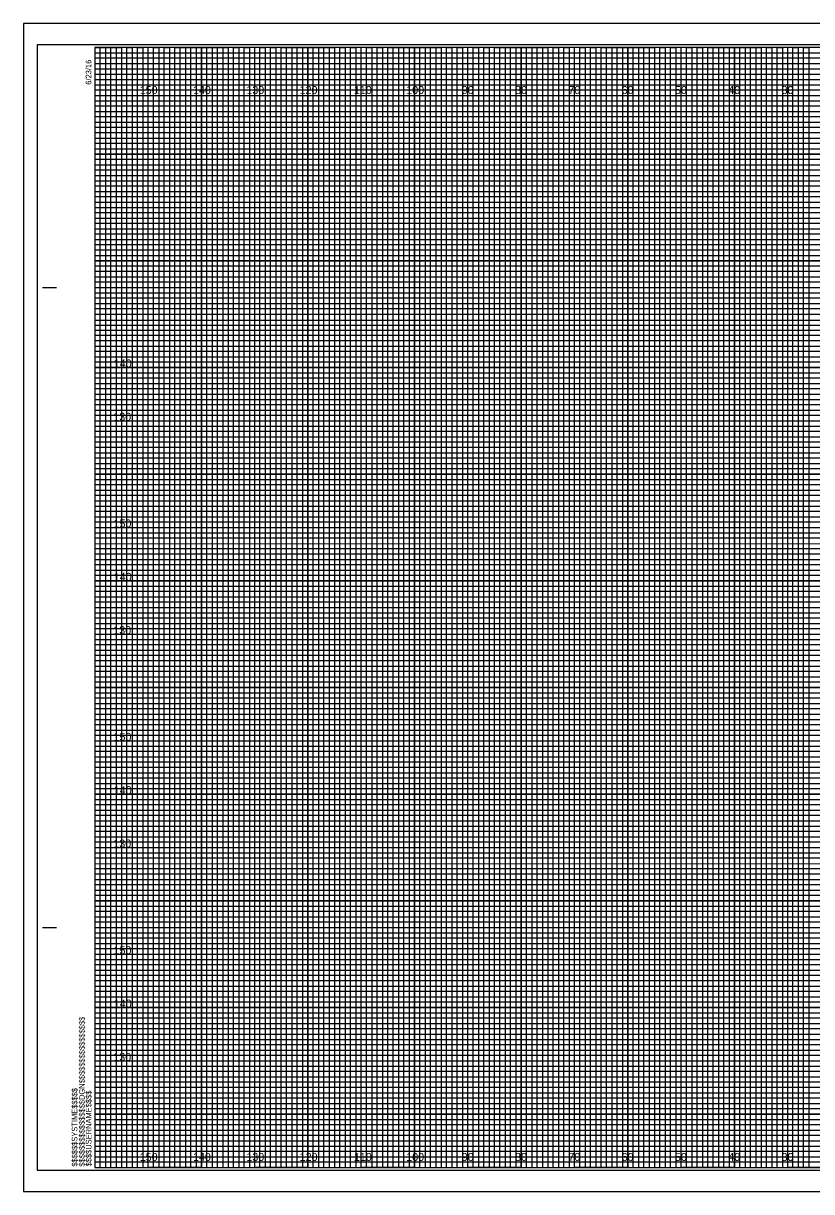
# Model space of a CAD drawing. Extents: x -13 to 323, y -5 to 434.
# Drawn here: x -13.4 to 134.5, y 215.5 to 434.5 of the extents above; entities that cross this region are included whole.
import ezdxf

# ---------------------------------------------------------------- set-up
doc = ezdxf.new("R2010")
doc.units = 0
for name, color, linetype in [('Exist Cross Section Cell', 7, 'Continuous'), ('Exist XS Center Line Elevation Label', 7, 'Continuous'), ('Exist XS Ground Line', 7, 'Continuous'), ('Prop CMT Pvmt Course 2', 7, 'Continuous'), ('Prop CMT Pvmt Course 3', 7, 'Continuous'), ('Prop CMT Pvmt Surface', 7, 'Continuous'), ('Prop CMT Pvmt Surface Shoulder', 7, 'Continuous'), ('Prop CMT Shld Paved Course 1', 7, 'Continuous'), ('Prop CMT Shld Paved Course 2', 7, 'Continuous'), ('Prop CMT Shld Paved Course 3', 7, 'Continuous'), ('Prop CMT Subgrade Earthwork', 7, 'Continuous')]:
    doc.layers.add(name, color=color, linetype=linetype)

msp = doc.modelspace()

# ---------------------------------------------------------------- linework, layer by layer
at = {"layer": 'Exist XS Center Line Elevation Label'}
for points in [[(0, 430), (5, 430), (5, 220), (15, 220), (15, 430), (25, 430), (25, 220), (35, 220), (35, 430), (45, 430), (45, 220), (55, 220), (55, 430), (65, 430), (65, 220), (75, 220), (75, 430), (85, 430), (85, 220), (95, 220), (95, 430), (105, 430), (105, 220), (115, 220), (115, 430), (125, 430), (125, 220), (135, 220)], [(0, 425), (275, 425)], [(0, 405), (320, 405), (320, 415), (0, 415)], [(0, 385), (320, 385), (320, 395), (0, 395)], [(0, 365), (320, 365), (320, 375), (0, 375)], [(0, 345), (320, 345), (320, 355), (0, 355)], [(0, 325), (320, 325), (320, 335), (0, 335)], [(0, 305), (320, 305), (320, 315), (0, 315)], [(0, 285), (320, 285), (320, 295), (0, 295)], [(0, 265), (320, 265), (320, 275), (0, 275)], [(0, 245), (320, 245), (320, 255), (0, 255)], [(0, 225), (320, 225), (320, 235), (0, 235)]]:
    msp.add_lwpolyline(points, dxfattribs=at)
at = {"layer": 'Exist XS Ground Line'}
for p, q in [((10, 430), (0, 430)), ((10, 220), (10, 430)), ((30, 430), (20, 430)), ((20, 430), (20, 220)), ((30, 220), (30, 430)), ((50, 430), (40, 430)), ((40, 430), (40, 220)), ((50, 220), (50, 430)), ((70, 430), (60, 430)), ((60, 430), (60, 220)), ((70, 220), (70, 430)), ((90, 430), (80, 430)), ((80, 430), (80, 220)), ((90, 220), (90, 430)), ((110, 430), (100, 430)), ((100, 430), (100, 220)), ((110, 220), (110, 430)), ((130, 430), (120, 430)), ((120, 430), (120, 220)), ((130, 220), (130, 430)), ((20, 220), (10, 220)), ((40, 220), (30, 220)), ((60, 220), (50, 220)), ((80, 220), (70, 220)), ((100, 220), (90, 220)), ((120, 220), (110, 220)), ((140, 220), (130, 220))]:
    msp.add_line(p, q, dxfattribs=at)
for points in [[(0, 420), (320, 420), (320, 410), (0, 410)], [(0, 400), (320, 400), (320, 390), (0, 390)], [(0, 380), (320, 380), (320, 370), (0, 370)], [(0, 360), (320, 360), (320, 350), (0, 350)], [(0, 340), (320, 340), (320, 330), (0, 330)], [(0, 320), (320, 320), (320, 310), (0, 310)], [(0, 300), (320, 300), (320, 290), (0, 290)], [(0, 280), (320, 280), (320, 270), (0, 270)], [(0, 260), (320, 260), (320, 250), (0, 250)], [(0, 240), (320, 240), (320, 230), (0, 230)]]:
    msp.add_lwpolyline(points, dxfattribs=at)
at = {"layer": 'Prop CMT Pvmt Course 2'}
for p, q in [((0, 429), (260, 429)), ((260, 427.98), (0, 427.98)), ((0, 427.98), (0, 427)), ((0, 427), (260, 427)), ((260, 425.89), (0, 425.89)), ((0, 425.89), (0, 424)), ((0, 424), (320, 424))]:
    msp.add_line(p, q, dxfattribs=at)
for points in [[(0, 423), (270, 423), (320, 423), (320, 422), (0, 422)], [(0, 421), (320, 421), (320, 419), (0, 419)], [(0, 418), (320, 418), (320, 417), (0, 416.98)], [(0, 416), (320, 416), (320, 414), (0, 414)], [(0, 413), (320, 413), (320, 412), (0, 412)], [(0, 411), (320, 411), (320, 409), (0, 409)], [(0, 408), (320, 408), (320, 407), (0, 407)], [(0, 406), (320, 406), (320, 404), (0, 404)], [(0, 403), (320, 403), (320, 402), (0, 402)], [(0, 401), (320, 401), (320, 399), (0, 399)], [(0, 398), (320, 398), (320, 397), (0, 397)], [(0, 396), (320, 396), (320, 393.95), (320, 393), (320, 392), (0, 392)], [(0, 394), (320, 394), (320, 393), (0, 393)], [(0, 391), (320, 391), (320, 389), (0, 389.03)], [(0, 389.03), (320, 389), (320, 388), (0, 388)], [(0, 387), (320, 387), (320, 386), (0, 386)], [(0, 384), (320, 384), (320, 383), (0, 383)], [(0, 382), (320, 382), (320, 381), (0, 381)], [(-0.07, 378.89), (320, 378.89), (320, 377.88), (-0.07, 377.88)], [(0, 377), (320, 377), (320, 376), (0, 376)], [(0, 374), (320, 374), (320, 373), (0, 373)], [(0, 372), (320, 372), (320, 371), (0, 371)], [(0, 369), (320, 369), (320, 368), (0, 368)], [(0, 367), (320, 367), (320, 366), (0, 366)], [(0, 364), (320, 364), (320, 363), (0, 363)], [(0, 362), (320, 362), (320, 361), (0, 361)], [(0, 359), (320, 359), (319.99, 357.98), (0, 358)], [(0, 357), (320, 357), (320, 356), (0, 356)], [(0, 354), (320, 354), (320, 353), (0, 353)], [(0, 352), (320, 352), (320, 351), (0, 351)], [(0, 349), (320, 349), (320, 348), (0, 348)], [(0, 347), (320, 347), (320, 346), (0, 346)], [(0, 344), (320, 344), (320, 343), (0, 343)], [(0, 342), (320, 342), (320, 341), (0, 341)], [(0, 339), (320, 339), (320, 338), (0, 338)], [(0, 336.99), (320.07, 336.91), (320, 336), (0, 336)], [(0, 334), (320, 334), (320, 333), (0, 333)], [(0, 332), (320, 332), (320, 331), (0, 331)], [(0, 329), (320, 329), (320, 328), (0, 328)], [(0, 327), (320, 327), (320, 326), (0, 326)], [(0, 324), (320, 324), (320, 323), (0, 323)], [(0, 322), (320, 322), (320, 321), (0, 321)], [(0, 319), (320, 319), (320, 318), (0, 318)], [(0, 317), (320, 317), (320, 316), (0, 316)], [(0, 314), (320, 314), (320, 313), (0, 313)], [(0, 312), (320, 312), (320, 311), (0, 311)], [(0, 309), (320, 309), (320, 308), (0, 308)], [(0, 307), (320, 307), (320, 306), (0, 306)], [(0, 304), (320, 304), (320, 303), (0, 303)], [(0, 302), (320, 302), (320, 301), (0, 301)], [(0, 299), (320, 299), (319.99, 297.98), (0, 298)], [(0, 297), (320, 297), (320, 296), (0, 296)], [(0, 294), (320, 294), (320, 293), (0, 293)], [(0, 292), (320, 292), (320, 291), (0, 291)], [(0, 289), (320, 289), (320, 288), (0, 288)], [(0, 287), (320, 287), (320, 286), (0, 286)], [(0, 284), (320, 284), (320, 283), (0, 283)], [(0, 282), (320, 282), (320, 281), (0, 281)], [(0, 279), (320, 279), (320, 278), (0, 278)], [(0, 276.99), (320.07, 276.91), (320, 276), (0, 276)], [(0, 274), (320, 274), (320, 273), (0, 273)], [(0, 272), (320, 272), (320, 271), (0, 271)], [(0, 269), (320, 269), (320, 268), (0, 268)], [(0, 267), (320, 267), (320, 266), (0, 266)], [(0, 264), (320, 264), (320, 263), (0, 263)], [(0, 262), (320, 262), (320, 261), (0, 261)], [(0, 259), (320, 259), (320, 258), (0, 258)], [(0, 257), (320, 257), (320, 256), (0, 256)], [(0, 254), (320, 254), (320, 253), (0, 253)], [(0, 252), (320, 252), (320, 251), (0, 251)], [(0, 249), (320, 249), (320, 248), (0, 248)], [(0, 247), (320, 247), (320, 246), (0, 246)], [(0, 244), (320, 244), (320, 243), (0, 243)], [(0, 242), (320, 242), (320, 241), (0, 241)], [(0, 239), (320, 239), (320, 238), (0, 238)], [(0, 237), (320, 237), (320, 236), (0, 236)], [(0, 234), (320, 234), (320, 233), (0, 233)], [(0, 232), (320, 232), (320, 231), (0, 231)], [(0, 229), (320, 229), (320, 228), (0, 228)], [(0, 227), (320, 227), (320, 226), (0, 226)], [(0, 224), (320, 224), (320, 223), (0, 223)], [(0, 222), (320, 222), (320, 221), (0, 221)]]:
    msp.add_lwpolyline(points, dxfattribs=at)
at = {"layer": 'Prop CMT Pvmt Course 3'}
for p, q in [((-9.8, 385), (-7.3, 385)), ((-9.7, 385), (-7.2, 385)), ((-9.8, 265), (-7.3, 265)), ((-9.7, 265), (-7.2, 265)), ((0, 220), (0, 220)), ((0, 220), (0, 220)), ((0, 220), (0, 220)), ((0, 220), (0, 220)), ((0, 220), (0, 220)), ((0, 220), (0, 220)), ((0, 220), (0, 220))]:
    msp.add_line(p, q, dxfattribs=at)
msp.add_lwpolyline([(320, 430), (0, 430), (0, 220), (320, 220)], close=True, dxfattribs=at)
at = {"layer": 'Prop CMT Pvmt Surface'}
for points in [[(0, 220), (1, 220), (1, 430), (2, 430), (2, 220)], [(2, 220), (3, 220), (3, 430), (4, 430), (4, 220)], [(5, 220), (6, 220), (6, 430), (7, 430), (7, 220)], [(7, 220), (8, 220), (8, 430), (9, 430), (9, 220)], [(10, 220), (11, 220), (11, 430), (12, 430), (12, 220)], [(12, 220), (13, 220), (13, 430), (14, 430), (14, 220)], [(15, 220), (16, 220), (16, 430), (17, 430), (17, 220)], [(17, 220), (18, 220), (18, 430), (19, 430), (19, 220)], [(20, 220), (21, 220), (21, 430), (22, 430), (22, 220)], [(22, 220), (23, 220), (23, 430), (24, 430), (24, 220)], [(25, 220), (26, 220), (26, 430), (27, 430), (27, 220)], [(27, 220), (28, 220), (28, 430), (29, 430), (29, 220)], [(30, 220), (31, 220), (31, 430), (32, 430), (32, 220)], [(32, 220), (33, 220), (33, 430), (34, 430), (34, 220)], [(35, 220), (36, 220), (36, 430), (37, 430), (37, 220)], [(37, 220), (38, 220), (38, 430), (39, 430), (39, 220)], [(40, 220), (41, 220), (41, 430), (42, 430), (42, 220)], [(42, 220), (43, 220), (43, 430), (44, 430), (44, 220)], [(45, 220), (46, 220), (46, 430), (47, 430), (47, 220)], [(47, 220), (48, 220), (48, 430), (49, 430), (49, 220)], [(50, 220), (51, 220), (51, 430), (52, 430), (52, 220)], [(52, 220), (53, 220), (53, 430), (54, 430), (54, 220)], [(55, 220), (56, 220), (56, 430), (57, 430), (57, 220)], [(57, 220), (58, 220), (58, 430), (59, 430), (59, 220)], [(60, 220), (61, 220), (61, 430), (62, 430), (62, 220)], [(62, 220), (63, 220), (63, 430), (64, 430), (64, 220)], [(65, 220), (66, 220), (66, 430), (67, 430), (67, 220)], [(67, 220), (68, 220), (68, 430), (69, 430), (69, 220)], [(70, 220), (71, 220), (71, 430), (72, 430), (72, 220)], [(72, 220), (73, 220), (73, 430), (74, 430), (74, 220)], [(75, 220), (76, 220), (76, 430), (77, 430), (77, 220)], [(77, 220), (78, 220), (78, 430), (79, 430), (79, 220)], [(80, 220), (81, 220), (81, 430), (82, 430), (82, 220)], [(82, 220), (83, 220), (83, 430), (84, 430), (84, 220)], [(85, 220), (86, 220), (86, 430), (87, 430), (87, 220)], [(87, 220), (88, 220), (88, 430), (89, 430), (89, 220)], [(90, 220), (91, 220), (91, 430), (92, 430), (92, 220)], [(92, 220), (93, 220), (93, 430), (94, 430), (94, 220)], [(95, 220), (96, 220), (96, 430), (97, 430), (97, 220)], [(97, 220), (98, 220), (98, 430), (99, 430), (99, 220)], [(100, 220), (101, 220), (101, 430), (102, 430), (102, 220)], [(102, 220), (103, 220), (103, 430), (104, 430), (104, 220)], [(105, 220), (106, 220), (106, 430), (107, 430), (107, 220)], [(107, 220), (108, 220), (108, 430), (109, 430), (109, 220)], [(110, 220), (111, 220), (111, 430), (112, 430), (112, 220)], [(112, 220), (113, 220), (113, 430), (114, 430), (114, 220)], [(115, 220), (116, 220), (116, 430), (117, 430), (117, 220)], [(117, 220), (118, 220), (118, 430), (119, 430), (119, 220)], [(120, 220), (121, 220), (121, 430), (122, 430), (122, 220)], [(122, 220), (123, 220), (123, 430), (124, 430), (124, 220)], [(125, 220), (126, 220), (126, 430), (127, 430), (127, 220)], [(127, 220), (128, 220), (128, 430), (129, 430), (129, 220)], [(130, 220), (131, 220), (131, 430), (132, 430), (132, 220)], [(132, 220), (133, 220), (133, 430), (134, 430), (134, 220)]]:
    msp.add_lwpolyline(points, dxfattribs=at)
at = {"layer": 'Prop CMT Pvmt Surface Shoulder'}
msp.add_lwpolyline([(-10.8, 219.5), (322.4, 219.5), (322.4, 430.5), (-10.8, 430.5)], close=True, dxfattribs=at)
at = {"layer": 'Prop CMT Shld Paved Course 1'}
for p, q in [((10, 220), (10, 430)), ((20, 220), (20, 430)), ((30, 220), (30, 430)), ((40, 220), (40, 430)), ((50, 220), (50, 430)), ((60, 220), (60, 430)), ((70, 220), (70, 430)), ((80, 220), (80, 430)), ((90, 220), (90, 430)), ((100, 220), (100, 430)), ((110, 220), (110, 430)), ((120, 220), (120, 430)), ((130, 220), (130, 430)), ((0, 420), (320, 420)), ((0, 410), (320, 410)), ((0, 400), (320, 400)), ((0, 390), (320, 390)), ((0, 380), (320, 380)), ((0, 370), (320, 370)), ((0, 360), (320, 360)), ((0, 350), (320, 350)), ((0, 340), (320, 340)), ((0, 330), (320, 330)), ((0, 320), (320, 320)), ((0, 310), (320, 310)), ((0, 300), (320, 300)), ((0, 290), (320, 290)), ((0, 280), (320, 280)), ((0, 270), (320, 270)), ((0, 260), (320, 260)), ((0, 250), (320, 250)), ((0, 240), (320, 240)), ((0, 230), (320, 230))]:
    msp.add_line(p, q, dxfattribs=at)
at = {"layer": 'Prop CMT Shld Paved Course 2'}
for p, q in [((323.3, 434.5), (-13.4, 434.5)), ((-13.4, 434.5), (-13.4, 215.5)), ((-13.4, 215.5), (323.3, 215.5))]:
    msp.add_line(p, q, dxfattribs=at)
at = {"layer": 'Prop CMT Subgrade Earthwork'}
msp.add_lwpolyline([(-13.4, 215.5), (323.3, 215.5), (323.3, 434.5), (-13.4, 434.5)], close=True, dxfattribs=at)

# ---------------------------------------------------------------- texts
at = {"layer": 'Exist Cross Section Cell'}
for s, p in [('150', (8.44, 421.25)), ('140', (18.44, 421.25)), ('130', (28.44, 421.25)), ('120', (38.44, 421.25)), ('110', (48.62, 421.25)), ('100', (58.44, 421.25)), ('90', (68.86, 421.25)), ('80', (78.86, 421.25)), ('70', (88.86, 421.25)), ('60', (98.86, 421.25)), ('50', (108.86, 421.25)), ('40', (118.86, 421.25)), ('30', (128.86, 421.25)), ('150', (8.44, 221.25)), ('140', (18.44, 221.25)), ('130', (28.44, 221.25)), ('120', (38.44, 221.25)), ('110', (48.62, 221.25)), ('100', (58.44, 221.25)), ('90', (68.86, 221.25)), ('80', (78.86, 221.25)), ('70', (88.86, 221.25)), ('60', (98.86, 221.25)), ('50', (108.86, 221.25)), ('40', (118.86, 221.25)), ('30', (128.86, 221.25))]:
    msp.add_text(s, height=1.5, dxfattribs=at).set_placement(p)
at = {"layer": 'Prop CMT Pvmt Course 3'}
for s, p in [('6/23/16', (-0.65, 423)), ('$$$$$$$$$$$$$$$$DGN$$$$$$$$$$$$$$$$', (-1.88, 220.18)), ('$$$$$$SYSTIME$$$$$', (-3.26, 220.18)), ('$$$$USERNAME$$$$', (-0.62, 220.23))]:
    msp.add_text(s, height=1.05, rotation=90, dxfattribs=at).set_placement(p)
at = {"layer": 'Prop CMT Shld Paved Course 3'}
for s, p in [('140', (3.57, 370)), ('130', (3.49, 360)), ('150', (3.52, 340)), ('140', (3.57, 330)), ('130', (3.49, 320)), ('150', (3.52, 300)), ('140', (3.57, 290)), ('130', (3.49, 280)), ('150', (3.52, 260)), ('140', (3.57, 250)), ('130', (3.49, 240))]:
    msp.add_text(s, height=1.5, dxfattribs=at).set_placement(p)

doc.saveas('drawing.dxf')
